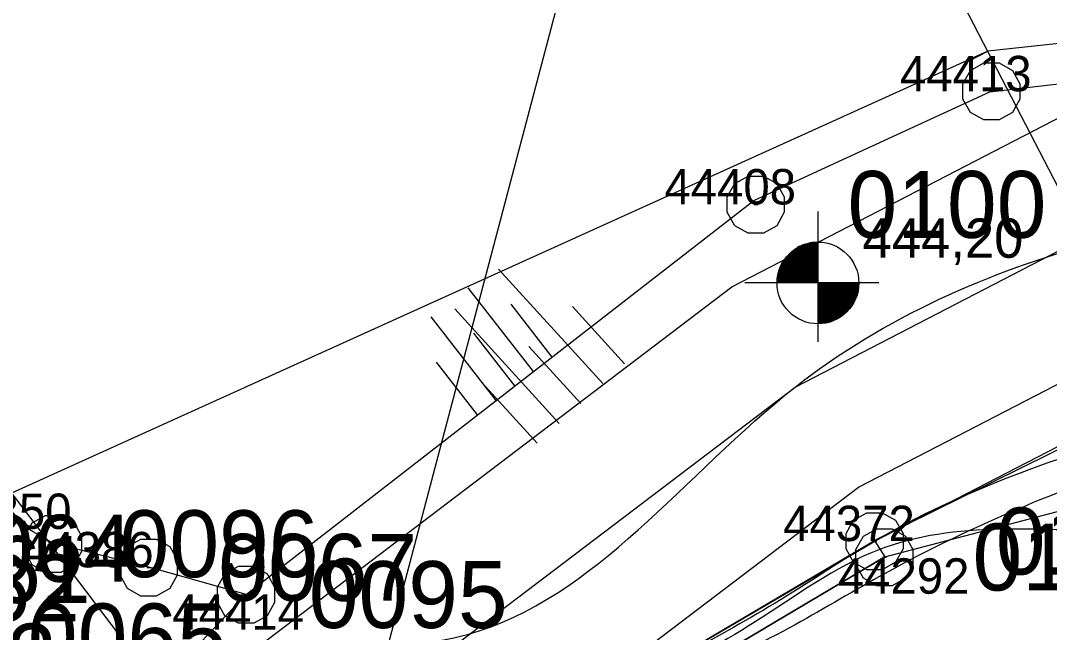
# Model space of a CAD drawing. Extents: x -598521 to -597689, y -1074676 to -1074150.
# Drawn here: x -598477.96 to -598464.88, y -1074167.68 to -1074159.9 of the extents above; entities that cross this region are included whole.
import ezdxf

# ---------------------------------------------------------------- set-up
doc = ezdxf.new("R2010")
doc.units = 0
for name, color, linetype in [('Vrstva 1', 7, 'Continuous'), ('Vrstva 10', 7, 'Continuous'), ('Vrstva 11', 7, 'Continuous'), ('Vrstva 12', 7, 'Continuous'), ('Vrstva 15', 7, 'Continuous'), ('Vrstva 2', 7, 'Continuous'), ('Vrstva 3', 7, 'Continuous'), ('Vrstva 5', 7, 'Continuous'), ('Vrstva 60', 7, 'Continuous'), ('Vrstva 61', 7, 'Continuous'), ('Vrstva 8', 7, 'Continuous')]:
    doc.layers.add(name, color=color, linetype=linetype)

msp = doc.modelspace()

# ---------------------------------------------------------------- linework, layer by layer
at = {"layer": 'Vrstva 1'}
for p, q in [((-598465.639, -1074160.801), (-598465.589, -1074160.801)), ((-598468.635, -1074162.24), (-598468.585, -1074162.24)), ((-598477.568, -1074166.554), (-598477.518, -1074166.554)), ((-598467.125, -1074166.52), (-598467.075, -1074166.52)), ((-598466.999, -1074166.723), (-598466.949, -1074166.723)), ((-598476.354, -1074166.854), (-598476.304, -1074166.854)), ((-598475.116, -1074167.2), (-598475.066, -1074167.2))]:
    msp.add_line(p, q, dxfattribs=at)
for points in [[(-598465.519, -1074160.441), (-598465.349, -1074160.536), (-598465.254, -1074160.706), (-598465.254, -1074160.901), (-598465.349, -1074161.071), (-598465.519, -1074161.166), (-598465.714, -1074161.166), (-598465.884, -1074161.071), (-598465.979, -1074160.901), (-598465.979, -1074160.706), (-598465.884, -1074160.536), (-598465.714, -1074160.441)], [(-598468.515, -1074161.88), (-598468.345, -1074161.975), (-598468.25, -1074162.145), (-598468.25, -1074162.34), (-598468.345, -1074162.51), (-598468.515, -1074162.605), (-598468.71, -1074162.605), (-598468.88, -1074162.51), (-598468.975, -1074162.34), (-598468.975, -1074162.145), (-598468.88, -1074161.975), (-598468.71, -1074161.88)], [(-598477.448, -1074166.194), (-598477.278, -1074166.289), (-598477.183, -1074166.459), (-598477.183, -1074166.654), (-598477.278, -1074166.824), (-598477.448, -1074166.919), (-598477.643, -1074166.919), (-598477.813, -1074166.824), (-598477.908, -1074166.654), (-598477.908, -1074166.459), (-598477.813, -1074166.289), (-598477.643, -1074166.194)], [(-598467.005, -1074166.16), (-598466.835, -1074166.255), (-598466.74, -1074166.425), (-598466.74, -1074166.62), (-598466.835, -1074166.79), (-598467.005, -1074166.885), (-598467.2, -1074166.885), (-598467.37, -1074166.79), (-598467.465, -1074166.62), (-598467.465, -1074166.425), (-598467.37, -1074166.255), (-598467.2, -1074166.16)], [(-598466.879, -1074166.363), (-598466.709, -1074166.458), (-598466.614, -1074166.628), (-598466.614, -1074166.823), (-598466.709, -1074166.993), (-598466.879, -1074167.088), (-598467.074, -1074167.088), (-598467.244, -1074166.993), (-598467.339, -1074166.823), (-598467.339, -1074166.628), (-598467.244, -1074166.458), (-598467.074, -1074166.363)], [(-598476.234, -1074166.494), (-598476.064, -1074166.589), (-598475.969, -1074166.759), (-598475.969, -1074166.954), (-598476.064, -1074167.124), (-598476.234, -1074167.219), (-598476.429, -1074167.219), (-598476.599, -1074167.124), (-598476.694, -1074166.954), (-598476.694, -1074166.759), (-598476.599, -1074166.589), (-598476.429, -1074166.494)], [(-598474.996, -1074166.84), (-598474.826, -1074166.935), (-598474.731, -1074167.105), (-598474.731, -1074167.3), (-598474.826, -1074167.47), (-598474.996, -1074167.565), (-598475.191, -1074167.565), (-598475.361, -1074167.47), (-598475.456, -1074167.3), (-598475.456, -1074167.105), (-598475.361, -1074166.935), (-598475.191, -1074166.84)]]:
    msp.add_lwpolyline(points, close=True, dxfattribs=at)
at = {"layer": 'Vrstva 10'}
for p, q in [((-598471.44, -1074164.364), (-598472.268, -1074163.299)), ((-598471.203, -1074164.18), (-598471.724, -1074163.509)), ((-598471.914, -1074164.732), (-598472.741, -1074163.667)), ((-598471.677, -1074164.548), (-598472.198, -1074163.877)), ((-598472.151, -1074164.916), (-598472.672, -1074164.246))]:
    msp.add_line(p, q, dxfattribs=at)
for points in [[(-598484.92, -1074215.734), (-598487.958, -1074208.491), (-598488.57, -1074195.13), (-598485.971, -1074186.446), (-598483.586, -1074182.241), (-598482.242, -1074177.742), (-598479.451, -1074171.782), (-598475.091, -1074167.2), (-598468.639, -1074162.188), (-598465.635, -1074160.81), (-598454.605, -1074159.518), (-598444.717, -1074161.464), (-598440.447, -1074163.564)], [(-598475.091, -1074167.2), (-598476.33, -1074166.85), (-598477.54, -1074166.55), (-598484.45, -1074162.57), (-598488.19, -1074160.407)], [(-598442.048, -1074219.486), (-598434.374, -1074208.569), (-598430.967, -1074201.161), (-598425.53, -1074195.272), (-598419.866, -1074189.628), (-598414.116, -1074180.898), (-598419.205, -1074177.506), (-598424.611, -1074174.962), (-598434.413, -1074170.349), (-598445.99, -1074163.97), (-598455.971, -1074163.301), (-598463.49, -1074164.656), (-598467.1, -1074166.52), (-598471.036, -1074168.831), (-598472.45, -1074170.18), (-598472.574, -1074170.302), (-598472.62, -1074170.36), (-598472.93, -1074170.67), (-598473.26, -1074171.05)], [(-598473.175, -1074171.129), (-598470.76, -1074168.97), (-598466.97, -1074166.72), (-598463.696, -1074165.859), (-598453.096, -1074164.71), (-598446.41, -1074166.04), (-598435.079, -1074171.773), (-598423.335, -1074177.929), (-598417.659, -1074181.967), (-598421.519, -1074188.787), (-598425.53, -1074192.947), (-598427.582, -1074193.806), (-598433.533, -1074199.431), (-598451.678, -1074206.463), (-598460.211, -1074206.905), (-598466.89, -1074208.495), (-598478.904, -1074213.937), (-598483.546, -1074205.944), (-598484.31, -1074196.25), (-598482.504, -1074189.522), (-598479.933, -1074184.345), (-598477.96, -1074180.01), (-598476.52, -1074177.56)]]:
    msp.add_lwpolyline(points, dxfattribs=at)
msp.add_lwpolyline([(-598473.273, -1074171.068), (-598472.93, -1074170.67), (-598472.62, -1074170.36), (-598472.45, -1074170.18), (-598471.036, -1074168.831), (-598467.1, -1074166.52), (-598466.97, -1074166.72), (-598470.76, -1074168.97), (-598471.967, -1074170.049), (-598473.175, -1074171.129)], close=True, dxfattribs=at)
at = {"layer": 'Vrstva 11'}
for p, q in [((-598471.16, -1074159.783), (-598473.892, -1074170.129)), ((-598470.559, -1074164.518), (-598471.882, -1074163.064)), ((-598471.114, -1074165.023), (-598472.437, -1074163.569)), ((-598470.281, -1074164.266), (-598470.943, -1074163.539)), ((-598470.836, -1074164.771), (-598471.498, -1074164.044)), ((-598471.391, -1074165.276), (-598472.053, -1074164.549))]:
    msp.add_line(p, q, dxfattribs=at)
at = {"layer": 'Vrstva 12'}
for points in [[(-598477.856, -1074175.904), (-598479.108, -1074177.873), (-598481.873, -1074181.144), (-598482.714, -1074182.62), (-598484.125, -1074188.19), (-598485.335, -1074196.141), (-598485.114, -1074200.364), (-598484.5, -1074206.655), (-598482.536, -1074211.254), (-598480.207, -1074214.488), (-598467.793, -1074210.214), (-598459.725, -1074208.727), (-598453.744, -1074207.761), (-598434.045, -1074202.26), (-598426.944, -1074195.607), (-598420.2, -1074189.398), (-598414.755, -1074180.164), (-598419.159, -1074177.729), (-598424.716, -1074175.666), (-598432.261, -1074171.95), (-598446.273, -1074165.334), (-598449.284, -1074163.066), (-598455.078, -1074161.455), (-598458.605, -1074161.801), (-598464.281, -1074162.718), (-598468.112, -1074164.562), (-598472.279, -1074167.706), (-598475.138, -1074168.205), (-598476.252, -1074168.916), (-598476.978, -1074169.714), (-598477.609, -1074175.205), (-598477.856, -1074175.904)], [(-598473.789, -1074172.039), (-598475.746, -1074175.895), (-598480.673, -1074186.045), (-598482.671, -1074189.544), (-598484.328, -1074196.236), (-598484.11, -1074202.306), (-598483.768, -1074206.314), (-598481.225, -1074209.94), (-598467.357, -1074209.735), (-598459.946, -1074208.147), (-598451.72, -1074206.172), (-598433.884, -1074198.944), (-598427.582, -1074193.806), (-598421.589, -1074188.753), (-598417.664, -1074181.613), (-598423.377, -1074177.475), (-598435.653, -1074170.84), (-598446.227, -1074166.125), (-598452.854, -1074164.125), (-598463.523, -1074165.086), (-598467.1, -1074166.52), (-598468.291, -1074167.262), (-598470.683, -1074168.7), (-598473.219, -1074171.071)], [(-598473.789, -1074172.039), (-598475.746, -1074175.895), (-598480.673, -1074186.045), (-598482.671, -1074189.544), (-598484.328, -1074196.236), (-598484.11, -1074202.306), (-598483.768, -1074206.314), (-598481.225, -1074209.94), (-598467.357, -1074209.735), (-598459.946, -1074208.147), (-598451.72, -1074206.172), (-598433.884, -1074198.944), (-598427.582, -1074193.806), (-598421.589, -1074188.753), (-598417.664, -1074181.613), (-598423.377, -1074177.475), (-598435.653, -1074170.84), (-598446.227, -1074166.125), (-598452.854, -1074164.125), (-598463.523, -1074165.086), (-598467.1, -1074166.52), (-598468.291, -1074167.262), (-598470.683, -1074168.7), (-598473.219, -1074171.071)], [(-598473.448, -1074172.233), (-598475.58, -1074175.922), (-598480.465, -1074186.125), (-598482.4, -1074189.73), (-598483.981, -1074196.229), (-598483.886, -1074202.253), (-598483.546, -1074205.944), (-598480.979, -1074209.161), (-598475.137, -1074210.074), (-598467.043, -1074208.93), (-598460.057, -1074207.659), (-598451.873, -1074205.694), (-598431.777, -1074196.461), (-598429.106, -1074194.199), (-598419.867, -1074184.797), (-598419.874, -1074181.816), (-598423.69, -1074178.164), (-598435.572, -1074171.16), (-598446.402, -1074166.594), (-598452.796, -1074164.414), (-598463.35, -1074165.396), (-598466.975, -1074166.935), (-598468.113, -1074167.583), (-598470.593, -1074168.979), (-598472.889, -1074171.361)], [(-598473.776, -1074172.057), (-598475.787, -1074175.805), (-598476.637, -1074177.247), (-598477.762, -1074179.285), (-598478.759, -1074181.512), (-598479.981, -1074184.111), (-598480.826, -1074187.623), (-598482.872, -1074196.644), (-598480.884, -1074204.447), (-598462.299, -1074205.951), (-598457.621, -1074205.244), (-598448.6, -1074200.236), (-598431.135, -1074190.052), (-598425.671, -1074182.345), (-598436.64, -1074172.436), (-598453.171, -1074165.178), (-598463.86, -1074166.401), (-598467.05, -1074166.63), (-598468.622, -1074167.548), (-598470.002, -1074168.369), (-598470.796, -1074168.897), (-598473.201, -1074171.085)]]:
    msp.add_spline(points, degree=3, dxfattribs=at)
at = {"layer": 'Vrstva 15'}
for p, q in [((-598459.843, -1074171.544), (-598469.032, -1074153.779)), ((-598469.033, -1074177.817), (-598481.127, -1074161.888))]:
    msp.add_line(p, q, dxfattribs=at)
at = {"layer": 'Vrstva 5'}
for points in [[(-598483.334, -1074182.678), (-598481.903, -1074179.345), (-598476.466, -1074169.022), (-598468.916, -1074163.289), (-598464.703, -1074161.11), (-598455.714, -1074160.021)], [(-598482.963, -1074215.515), (-598486.401, -1074207.525), (-598486.999, -1074195.022), (-598480.548, -1074179.991), (-598475.294, -1074170.015), (-598468.112, -1074164.562), (-598464.254, -1074162.567), (-598455.078, -1074161.455), (-598445.366, -1074162.766), (-598432.996, -1074169.084), (-598417.866, -1074175.801), (-598412.373, -1074178.959)], [(-598480.641, -1074184.01), (-598479.193, -1074180.638), (-598474.122, -1074171.009), (-598467.307, -1074165.835), (-598463.805, -1074164.023), (-598455.361, -1074163)]]:
    msp.add_lwpolyline(points, dxfattribs=at)
at = {"layer": 'Vrstva 60'}
msp.add_lwpolyline([(-598465.9, -1074160.412), (-598465.664, -1074160.29)], dxfattribs=at)
at = {"layer": 'Vrstva 61'}
msp.add_lwpolyline([(-598485.86, -1074181.592), (-598487.335, -1074191.113), (-598484.15, -1074192.479), (-598480.117, -1074184.058), (-598478.152, -1074179.86), (-598476.74, -1074177.23), (-598476.61, -1074175.53), (-598476.12, -1074174.39), (-598475.294, -1074173.013), (-598474.79, -1074172.185), (-598474.564, -1074171.737), (-598475.58, -1074171.07), (-598474.774, -1074169.84), (-598473.651, -1074170.579), (-598471.036, -1074168.831), (-598467.081, -1074166.5), (-598463.394, -1074164.678), (-598455.303, -1074163.295), (-598452.559, -1074163.532), (-598452.084, -1074160.017), (-598455.796, -1074159.225), (-598465.664, -1074160.29), (-598478.074, -1074165.91)], close=True, dxfattribs=at)
at = {"layer": 'Vrstva 8'}
for p, q in [((-598467.822, -1074162.33), (-598467.822, -1074163.985)), ((-598467.826, -1074162.839), (-598468.152, -1074162.839)), ((-598467.826, -1074162.834), (-598468.146, -1074162.834)), ((-598467.826, -1074162.829), (-598468.139, -1074162.829)), ((-598467.826, -1074162.824), (-598468.133, -1074162.824)), ((-598467.826, -1074162.819), (-598468.126, -1074162.819)), ((-598467.826, -1074162.814), (-598468.12, -1074162.814)), ((-598467.826, -1074162.809), (-598468.114, -1074162.809)), ((-598467.826, -1074162.804), (-598468.107, -1074162.804)), ((-598467.826, -1074162.799), (-598468.101, -1074162.799)), ((-598467.826, -1074162.794), (-598468.094, -1074162.794)), ((-598467.826, -1074162.789), (-598468.088, -1074162.789)), ((-598467.826, -1074162.784), (-598468.082, -1074162.784)), ((-598467.826, -1074162.779), (-598468.075, -1074162.779)), ((-598467.826, -1074162.774), (-598468.064, -1074162.774)), ((-598467.826, -1074162.769), (-598468.051, -1074162.769)), ((-598467.826, -1074162.764), (-598468.037, -1074162.764)), ((-598467.826, -1074162.759), (-598468.023, -1074162.759)), ((-598467.826, -1074162.754), (-598468.009, -1074162.754)), ((-598467.826, -1074162.749), (-598467.996, -1074162.749)), ((-598467.826, -1074162.744), (-598467.982, -1074162.744)), ((-598467.826, -1074162.739), (-598467.961, -1074162.739)), ((-598467.826, -1074162.734), (-598467.94, -1074162.734)), ((-598467.826, -1074162.729), (-598467.919, -1074162.729)), ((-598467.826, -1074162.724), (-598467.898, -1074162.724)), ((-598467.826, -1074162.969), (-598468.269, -1074162.969)), ((-598467.826, -1074162.964), (-598468.267, -1074162.964)), ((-598467.826, -1074162.959), (-598468.264, -1074162.959)), ((-598467.826, -1074162.954), (-598468.261, -1074162.954)), ((-598467.826, -1074162.949), (-598468.259, -1074162.949)), ((-598467.826, -1074162.944), (-598468.255, -1074162.944)), ((-598467.826, -1074162.939), (-598468.25, -1074162.939)), ((-598467.826, -1074162.934), (-598468.245, -1074162.934)), ((-598467.826, -1074162.929), (-598468.241, -1074162.929)), ((-598467.826, -1074162.924), (-598468.236, -1074162.924)), ((-598467.826, -1074162.919), (-598468.232, -1074162.919)), ((-598467.826, -1074162.914), (-598468.227, -1074162.914)), ((-598467.826, -1074162.909), (-598468.222, -1074162.909)), ((-598467.826, -1074162.904), (-598468.218, -1074162.904)), ((-598467.826, -1074162.899), (-598468.213, -1074162.899)), ((-598467.826, -1074162.894), (-598468.209, -1074162.894)), ((-598467.826, -1074162.889), (-598468.204, -1074162.889)), ((-598467.826, -1074162.884), (-598468.199, -1074162.884)), ((-598467.826, -1074162.879), (-598468.195, -1074162.879)), ((-598467.826, -1074162.874), (-598468.19, -1074162.874)), ((-598467.826, -1074162.869), (-598468.186, -1074162.869)), ((-598467.826, -1074162.864), (-598468.181, -1074162.864)), ((-598467.826, -1074162.859), (-598468.177, -1074162.859)), ((-598467.826, -1074162.854), (-598468.171, -1074162.854)), ((-598467.826, -1074162.849), (-598468.165, -1074162.849)), ((-598467.826, -1074162.844), (-598468.158, -1074162.844)), ((-598467.826, -1074163.104), (-598468.323, -1074163.104)), ((-598467.826, -1074163.094), (-598468.322, -1074163.094)), ((-598467.826, -1074163.099), (-598468.322, -1074163.099)), ((-598467.826, -1074163.089), (-598468.321, -1074163.089)), ((-598467.826, -1074163.084), (-598468.32, -1074163.084)), ((-598467.826, -1074163.079), (-598468.319, -1074163.079)), ((-598467.826, -1074163.069), (-598468.318, -1074163.069)), ((-598467.826, -1074163.074), (-598468.318, -1074163.074)), ((-598467.826, -1074163.064), (-598468.317, -1074163.064)), ((-598467.826, -1074163.059), (-598468.316, -1074163.059)), ((-598467.826, -1074163.054), (-598468.314, -1074163.054)), ((-598467.826, -1074163.049), (-598468.312, -1074163.049)), ((-598467.826, -1074163.044), (-598468.309, -1074163.044)), ((-598467.826, -1074163.039), (-598468.306, -1074163.039)), ((-598467.826, -1074163.034), (-598468.304, -1074163.034)), ((-598467.826, -1074163.029), (-598468.301, -1074163.029)), ((-598467.826, -1074163.024), (-598468.298, -1074163.024)), ((-598467.826, -1074163.019), (-598468.296, -1074163.019)), ((-598467.826, -1074163.014), (-598468.293, -1074163.014)), ((-598467.826, -1074163.009), (-598468.29, -1074163.009)), ((-598467.826, -1074163.004), (-598468.288, -1074163.004)), ((-598467.826, -1074162.999), (-598468.285, -1074162.999)), ((-598467.826, -1074162.994), (-598468.282, -1074162.994)), ((-598467.826, -1074162.989), (-598468.28, -1074162.989)), ((-598467.826, -1074162.984), (-598468.277, -1074162.984)), ((-598467.826, -1074162.979), (-598468.275, -1074162.979)), ((-598467.826, -1074162.974), (-598468.272, -1074162.974)), ((-598467.826, -1074163.234), (-598468.341, -1074163.234)), ((-598467.826, -1074163.229), (-598468.34, -1074163.229)), ((-598467.826, -1074163.219), (-598468.339, -1074163.219)), ((-598467.826, -1074163.224), (-598468.339, -1074163.224)), ((-598467.826, -1074163.209), (-598468.338, -1074163.209)), ((-598467.826, -1074163.214), (-598468.338, -1074163.214)), ((-598467.826, -1074163.204), (-598468.337, -1074163.204)), ((-598467.826, -1074163.194), (-598468.336, -1074163.194)), ((-598467.826, -1074163.199), (-598468.336, -1074163.199)), ((-598467.826, -1074163.189), (-598468.335, -1074163.189)), ((-598467.826, -1074163.179), (-598468.334, -1074163.179)), ((-598467.826, -1074163.184), (-598468.334, -1074163.184)), ((-598467.826, -1074163.169), (-598468.333, -1074163.169)), ((-598467.826, -1074163.174), (-598468.333, -1074163.174)), ((-598467.826, -1074163.164), (-598468.332, -1074163.164)), ((-598467.826, -1074163.154), (-598468.331, -1074163.154)), ((-598467.826, -1074163.159), (-598468.331, -1074163.159)), ((-598467.826, -1074163.149), (-598468.33, -1074163.149)), ((-598467.826, -1074163.144), (-598468.329, -1074163.144)), ((-598467.826, -1074163.134), (-598468.328, -1074163.134)), ((-598467.826, -1074163.139), (-598468.328, -1074163.139)), ((-598467.826, -1074163.129), (-598468.327, -1074163.129)), ((-598467.826, -1074163.124), (-598468.326, -1074163.124)), ((-598467.826, -1074163.114), (-598468.325, -1074163.114)), ((-598467.826, -1074163.119), (-598468.325, -1074163.119)), ((-598467.826, -1074163.109), (-598468.324, -1074163.109)), ((-598467.05, -1074163.238), (-598468.751, -1074163.238)), ((-598467.302, -1074163.278), (-598467.823, -1074163.278)), ((-598467.302, -1074163.283), (-598467.823, -1074163.283)), ((-598467.303, -1074163.288), (-598467.823, -1074163.288)), ((-598467.303, -1074163.293), (-598467.823, -1074163.293)), ((-598467.303, -1074163.298), (-598467.823, -1074163.298)), ((-598467.303, -1074163.303), (-598467.823, -1074163.303)), ((-598467.304, -1074163.308), (-598467.823, -1074163.308)), ((-598467.304, -1074163.313), (-598467.823, -1074163.313)), ((-598467.306, -1074163.318), (-598467.823, -1074163.318)), ((-598467.307, -1074163.323), (-598467.823, -1074163.323)), ((-598467.309, -1074163.328), (-598467.823, -1074163.328)), ((-598467.31, -1074163.333), (-598467.823, -1074163.333)), ((-598467.311, -1074163.338), (-598467.823, -1074163.338)), ((-598467.313, -1074163.343), (-598467.823, -1074163.343)), ((-598467.314, -1074163.348), (-598467.823, -1074163.348)), ((-598467.316, -1074163.353), (-598467.823, -1074163.353)), ((-598467.317, -1074163.358), (-598467.823, -1074163.358)), ((-598467.318, -1074163.363), (-598467.823, -1074163.363)), ((-598467.3, -1074163.243), (-598467.822, -1074163.243)), ((-598467.3, -1074163.248), (-598467.822, -1074163.248)), ((-598467.301, -1074163.253), (-598467.822, -1074163.253)), ((-598467.301, -1074163.258), (-598467.822, -1074163.258)), ((-598467.301, -1074163.263), (-598467.822, -1074163.263)), ((-598467.301, -1074163.268), (-598467.822, -1074163.268)), ((-598467.302, -1074163.273), (-598467.822, -1074163.273)), ((-598467.335, -1074163.423), (-598467.824, -1074163.423)), ((-598467.337, -1074163.428), (-598467.824, -1074163.428)), ((-598467.338, -1074163.433), (-598467.824, -1074163.433)), ((-598467.339, -1074163.438), (-598467.824, -1074163.438)), ((-598467.341, -1074163.443), (-598467.824, -1074163.443)), ((-598467.342, -1074163.448), (-598467.824, -1074163.448)), ((-598467.344, -1074163.453), (-598467.824, -1074163.453)), ((-598467.347, -1074163.458), (-598467.824, -1074163.458)), ((-598467.351, -1074163.463), (-598467.824, -1074163.463)), ((-598467.354, -1074163.468), (-598467.824, -1074163.468)), ((-598467.357, -1074163.473), (-598467.824, -1074163.473)), ((-598467.361, -1074163.478), (-598467.824, -1074163.478)), ((-598467.364, -1074163.483), (-598467.824, -1074163.483)), ((-598467.367, -1074163.488), (-598467.824, -1074163.488)), ((-598467.371, -1074163.493), (-598467.824, -1074163.493)), ((-598467.32, -1074163.368), (-598467.823, -1074163.368)), ((-598467.321, -1074163.373), (-598467.823, -1074163.373)), ((-598467.322, -1074163.378), (-598467.823, -1074163.378)), ((-598467.324, -1074163.383), (-598467.823, -1074163.383)), ((-598467.325, -1074163.388), (-598467.823, -1074163.388)), ((-598467.327, -1074163.393), (-598467.823, -1074163.393)), ((-598467.328, -1074163.398), (-598467.823, -1074163.398)), ((-598467.329, -1074163.403), (-598467.823, -1074163.403)), ((-598467.331, -1074163.408), (-598467.823, -1074163.408)), ((-598467.332, -1074163.413), (-598467.823, -1074163.413)), ((-598467.334, -1074163.418), (-598467.823, -1074163.418)), ((-598467.434, -1074163.573), (-598467.825, -1074163.573)), ((-598467.438, -1074163.578), (-598467.825, -1074163.578)), ((-598467.443, -1074163.583), (-598467.825, -1074163.583)), ((-598467.448, -1074163.588), (-598467.825, -1074163.588)), ((-598467.452, -1074163.593), (-598467.825, -1074163.593)), ((-598467.457, -1074163.598), (-598467.825, -1074163.598)), ((-598467.462, -1074163.603), (-598467.825, -1074163.603)), ((-598467.467, -1074163.608), (-598467.825, -1074163.608)), ((-598467.471, -1074163.613), (-598467.825, -1074163.613)), ((-598467.476, -1074163.618), (-598467.825, -1074163.618)), ((-598467.48, -1074163.623), (-598467.825, -1074163.623)), ((-598467.374, -1074163.498), (-598467.824, -1074163.498)), ((-598467.378, -1074163.503), (-598467.824, -1074163.503)), ((-598467.381, -1074163.508), (-598467.824, -1074163.508)), ((-598467.384, -1074163.513), (-598467.824, -1074163.513)), ((-598467.388, -1074163.518), (-598467.824, -1074163.518)), ((-598467.391, -1074163.523), (-598467.824, -1074163.523)), ((-598467.394, -1074163.528), (-598467.824, -1074163.528)), ((-598467.398, -1074163.533), (-598467.824, -1074163.533)), ((-598467.401, -1074163.538), (-598467.824, -1074163.538)), ((-598467.406, -1074163.543), (-598467.824, -1074163.543)), ((-598467.41, -1074163.548), (-598467.824, -1074163.548)), ((-598467.415, -1074163.553), (-598467.824, -1074163.553)), ((-598467.42, -1074163.558), (-598467.824, -1074163.558)), ((-598467.424, -1074163.563), (-598467.824, -1074163.563)), ((-598467.429, -1074163.568), (-598467.824, -1074163.568)), ((-598467.628, -1074163.718), (-598467.826, -1074163.718)), ((-598467.643, -1074163.723), (-598467.826, -1074163.723)), ((-598467.663, -1074163.728), (-598467.826, -1074163.728)), ((-598467.682, -1074163.733), (-598467.826, -1074163.733)), ((-598467.702, -1074163.738), (-598467.826, -1074163.738)), ((-598467.723, -1074163.743), (-598467.826, -1074163.743)), ((-598467.751, -1074163.748), (-598467.826, -1074163.748)), ((-598467.779, -1074163.753), (-598467.826, -1074163.753)), ((-598467.485, -1074163.628), (-598467.825, -1074163.628)), ((-598467.49, -1074163.633), (-598467.825, -1074163.633)), ((-598467.494, -1074163.638), (-598467.825, -1074163.638)), ((-598467.499, -1074163.643), (-598467.825, -1074163.643)), ((-598467.504, -1074163.648), (-598467.825, -1074163.648)), ((-598467.508, -1074163.653), (-598467.825, -1074163.653)), ((-598467.515, -1074163.658), (-598467.825, -1074163.658)), ((-598467.524, -1074163.663), (-598467.825, -1074163.663)), ((-598467.532, -1074163.668), (-598467.825, -1074163.668)), ((-598467.541, -1074163.673), (-598467.825, -1074163.673)), ((-598467.549, -1074163.678), (-598467.825, -1074163.678)), ((-598467.558, -1074163.683), (-598467.825, -1074163.683)), ((-598467.566, -1074163.688), (-598467.825, -1074163.688)), ((-598467.575, -1074163.693), (-598467.825, -1074163.693)), ((-598467.586, -1074163.698), (-598467.825, -1074163.698)), ((-598467.597, -1074163.703), (-598467.825, -1074163.703)), ((-598467.607, -1074163.708), (-598467.825, -1074163.708)), ((-598467.618, -1074163.713), (-598467.825, -1074163.713))]:
    msp.add_line(p, q, dxfattribs=at)
msp.add_circle((-598467.822, -1074163.238), 0.52, dxfattribs=at)

# ---------------------------------------------------------------- texts
at = {"layer": 'Vrstva 11'}
msp.add_text('444,20', height=0.5, dxfattribs=at).set_placement((-598467.255, -1074162.918))
at = {"layer": 'Vrstva 2'}
for s, p in [('0100', (-598467.446, -1074162.665)), ('0101', (-598465.561, -1074166.945)), ('0064', (-598479.058, -1074167.036)), ('0096', (-598476.7, -1074166.979)), ('0102', (-598465.856, -1074167.148)), ('0061', (-598479.598, -1074167.306)), ('0067', (-598475.446, -1074167.279)), ('0062', (-598479.734, -1074167.54)), ('0095', (-598474.295, -1074167.625)), ('0065', (-598477.866, -1074168.163)), ('0063', (-598480.029, -1074168.42))]:
    msp.add_text(s, height=0.85, dxfattribs=at).set_placement(p)
at = {"layer": 'Vrstva 3'}
for s, p in [('44413', (-598466.779, -1074160.801)), ('44408', (-598469.774, -1074162.24)), ('44350', (-598478.985, -1074166.366)), ('44372', (-598468.264, -1074166.52)), ('44386', (-598477.941, -1074166.854)), ('44292', (-598467.569, -1074167.189)), ('44414', (-598476.031, -1074167.648))]:
    msp.add_text(s, height=0.45, dxfattribs=at).set_placement(p)

doc.saveas('drawing.dxf')
